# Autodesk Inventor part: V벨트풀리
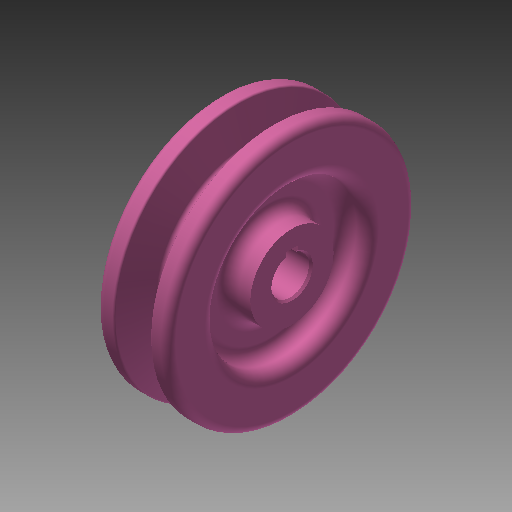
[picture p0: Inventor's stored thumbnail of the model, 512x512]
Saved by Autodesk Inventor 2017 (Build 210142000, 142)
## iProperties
Created: 2015-11
Part Number: V벨트풀리
Material: 강철, 탄소
Document SubType Name: Modeling
Designer: mduedu
Density: 1 g/cm^3
Appearance: 분홍색
Author: mduedu
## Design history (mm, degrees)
sketch "스케치1"
  geometry: L1 (-9.5, 0)-(9.5, 0); L2 (0, 0)-(0, 32.7); L3 (-4.825, 32.7)-(-9.5, 32.7); L4 (-9.5, 32.7)-(-9.5, 0); L5 (0, 23.7)-(-2.074, 23.7); L6 (-2.074, 23.7)-(-4.825, 32.7); L7 (4.825, 32.7)-(9.5, 32.7); L8 (9.5, 32.7)-(9.5, 0); L9 (0, 23.7)-(2.074, 23.7); L10 (2.074, 23.7)-(4.825, 32.7); L11 (-9.5, 30)-(9.5, 30); 3 further points
  constraints: 22 end point, 7 point on line, 4 perpendicular, 3 symmetric about line, 1 coincident, 1 horizontal, 1 horizontal alignment, 1 midpoint, 1 vertical
  dimensions: "d0" = 19 distance of L1.start L1.end; "d2" = 65.4 diameter of L2.end L1 (derived); "d3" = 34 deg angle of L10 L6; "d4" = 6.3 distance between parallel lines of L11 L9; "d5" = 2.7 distance between parallel lines of L7 L11; "d6" = 8 distance of point (4, 30) point (-4, 30); "d7" = 60 diameter of L11 L1
revolve "회전1" sketch "스케치1" stored, may be unused: angle "d8" = 90 deg
sketch "스케치2"
  geometry: C1 r 20 at (0, 0); C2 r 11 at (0, 0); 1 further point
  constraints: 2 centre point, 2 coincident
  dimensions: "d9" = 40 diameter of C1; "d10" = 22 diameter of C2
extrude "돌출1" cut sketch "스케치2" distance "d11" = 6; taper "d12" = 0 deg
fillet "모깎기1" dims "d13" = 3
fillet "모깎기2" dims "d14" = 3
fillet "모깎기3" dims "d15" = 1, "d16" = 0.5, "d17" = 2
hole "구멍1" diameter "d20" = 10; stored, may be unused: countersink angle "d24" = 90 deg, drill point angle "d26" = 118 deg; dims "d18" = 10, "d19" = 10, "d21" = 6, "d22" = 4, "d23" = 2, "d25" = 8
sketch "스케치3"
  geometry: L1 (-1.5, 0)-(1.5, 0); L2 (1.5, 0)-(1.5, 6.4); L3 (1.5, 6.4)-(-1.5, 6.4); L4 (-1.5, 6.4)-(-1.5, 0); 2 further points
  constraints: 8 end point, 2 parallel, 1 coincident, 1 horizontal, 1 midpoint, 1 perpendicular
  dimensions: "d27" = 3 distance of L2.end L3.end; "d29" = 6.4 distance of L3.end L1.start
extrude "돌출2" cut sketch "스케치3" stored distance "d30" = 6; taper "d31" = 0 deg
chamfer "모따기1" distance "d32" = 0.5; stored, may be unused: second distance "d33" = 2, angle "d34" = 45 deg
node "솔리드1"
mirror "대칭1"
